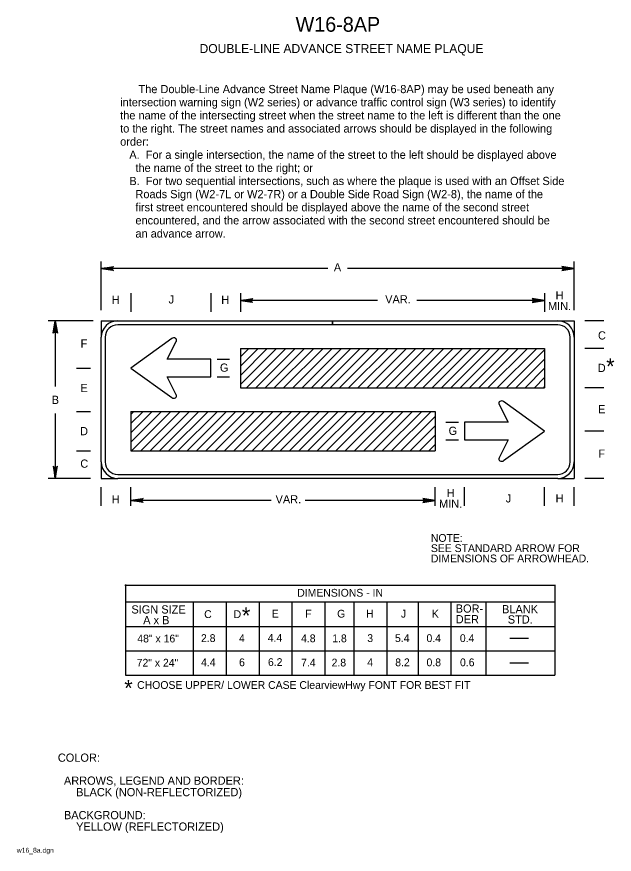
# Model space of a CAD drawing. Extents: x 0.013 to 0.195, y 0.004 to 0.259.
import ezdxf

# ---------------------------------------------------------------- set-up
doc = ezdxf.new("R2010")
doc.units = 0
for name, color, linetype in [('1', 7, 'Continuous'), ('2', 7, 'Continuous'), ('3', 7, 'Continuous')]:
    doc.layers.add(name, color=color, linetype=linetype)

# ---------------------------------------------------------------- blocks, each defined once
blk = doc.blocks.new('RARROW')
at = {"layer": '3'}
for p, q in [((-2.156, 0.285), (-2.2665, 0.384625)), ((-2.2665, 0.384625), (0, 0)), ((0, 0), (-2.2665, -0.379125)), ((-2.156, 0.285), (-2.075625, 0.12075)), ((0, 0), (-2.156, 0.285)), ((-2.14975, -0.2705), (0, 0)), ((-2.075625, 0.12075), (0, 0)), ((0, 0), (-2.074, -0.108)), ((-2.2665, -0.379125), (-2.14975, -0.2705)), ((-2.074, -0.108), (-2.14975, -0.2705))]:
    blk.add_line(p, q, dxfattribs=at)

msp = doc.modelspace()

# ---------------------------------------------------------------- linework, layer by layer
at = {"layer": '1'}
for p, q in [((0.04735, 0.17484), (0.04735, 0.16912)), ((0.0717, 0.17484), (0.0717, 0.16912)), ((0.0807, 0.17484), (0.0807, 0.16912)), ((0.17335, 0.17484), (0.17335, 0.16912)), ((0.02436, 0.16643), (0.02436, 0.14645)), ((0.03835, 0.16643), (0.03835, 0.16143)), ((0.04335, 0.16643), (0.10877, 0.16643)), ((0.10877, 0.16643), (0.10877, 0.16523)), ((0.10877, 0.16523), (0.10877, 0.16643)), ((0.10877, 0.16643), (0.17735, 0.16643)), ((0.18235, 0.16643), (0.18235, 0.16143)), ((0.10877, 0.16523), (0.04335, 0.16523)), ((0.17735, 0.16523), (0.10877, 0.16523)), ((0.03835, 0.12343), (0.03835, 0.16143)), ((0.03955, 0.16143), (0.03955, 0.12343)), ((0.05982, 0.16103), (0.04735, 0.15203)), ((0.18115, 0.12343), (0.18115, 0.16143)), ((0.18235, 0.16143), (0.18235, 0.12343)), ((0.05841, 0.15473), (0.06118, 0.16015)), ((0.0807, 0.15803), (0.0807, 0.14603)), ((0.0807, 0.15547), (0.08325, 0.15803)), ((0.0807, 0.15265), (0.08608, 0.15803)), ((0.0807, 0.14982), (0.08891, 0.15803)), ((0.0807, 0.14699), (0.09174, 0.15803)), ((0.08257, 0.14603), (0.09457, 0.15803)), ((0.08539, 0.14603), (0.09739, 0.15803)), ((0.08822, 0.14603), (0.10022, 0.15803)), ((0.09105, 0.14603), (0.10305, 0.15803)), ((0.09388, 0.14603), (0.10588, 0.15803)), ((0.09671, 0.14603), (0.10871, 0.15803)), ((0.09954, 0.14603), (0.11154, 0.15803)), ((0.10237, 0.14603), (0.11437, 0.15803)), ((0.10519, 0.14603), (0.11719, 0.15803)), ((0.10802, 0.14603), (0.12002, 0.15803)), ((0.11085, 0.14603), (0.12285, 0.15803)), ((0.11368, 0.14603), (0.12568, 0.15803)), ((0.11651, 0.14603), (0.12851, 0.15803)), ((0.11934, 0.14603), (0.13134, 0.15803)), ((0.12216, 0.14603), (0.13416, 0.15803)), ((0.12499, 0.14603), (0.13699, 0.15803)), ((0.12782, 0.14603), (0.13982, 0.15803)), ((0.13065, 0.14603), (0.14265, 0.15803)), ((0.13348, 0.14603), (0.14548, 0.15803)), ((0.13631, 0.14603), (0.14831, 0.15803)), ((0.13913, 0.14603), (0.15113, 0.15803)), ((0.14196, 0.14603), (0.15396, 0.15803)), ((0.14479, 0.14603), (0.15679, 0.15803)), ((0.14762, 0.14603), (0.15962, 0.15803)), ((0.15045, 0.14603), (0.16245, 0.15803)), ((0.15328, 0.14603), (0.16528, 0.15803)), ((0.15611, 0.14603), (0.16811, 0.15803)), ((0.15893, 0.14603), (0.17093, 0.15803)), ((0.16176, 0.14603), (0.17335, 0.15761)), ((0.17335, 0.15803), (0.17335, 0.14603)), ((0.0717, 0.15473), (0.05841, 0.15473)), ((0.0717, 0.14933), (0.0717, 0.15473)), ((0.16459, 0.14603), (0.17335, 0.15479)), ((0.04735, 0.15203), (0.05982, 0.14303)), ((0.16742, 0.14603), (0.17335, 0.15196)), ((0.06118, 0.1439), (0.05841, 0.14933)), ((0.05841, 0.14933), (0.0717, 0.14933)), ((0.17025, 0.14603), (0.17335, 0.14913)), ((0.17308, 0.14603), (0.17335, 0.1463)), ((0.15952, 0.14095), (0.16229, 0.13553)), ((0.17335, 0.13283), (0.16087, 0.14183)), ((0.02436, 0.13816), (0.02436, 0.11843)), ((0.04735, 0.13883), (0.04735, 0.12683)), ((0.04735, 0.13793), (0.04825, 0.13883)), ((0.04735, 0.1351), (0.05108, 0.13883)), ((0.04735, 0.13227), (0.0539, 0.13883)), ((0.04735, 0.12944), (0.05673, 0.13883)), ((0.04756, 0.12683), (0.05956, 0.13883)), ((0.05039, 0.12683), (0.06239, 0.13883)), ((0.05322, 0.12683), (0.06522, 0.13883)), ((0.05605, 0.12683), (0.06805, 0.13883)), ((0.05887, 0.12683), (0.07087, 0.13883)), ((0.0617, 0.12683), (0.0737, 0.13883)), ((0.06453, 0.12683), (0.07653, 0.13883)), ((0.06736, 0.12683), (0.07936, 0.13883)), ((0.07019, 0.12683), (0.08219, 0.13883)), ((0.07302, 0.12683), (0.08502, 0.13883)), ((0.07585, 0.12683), (0.08785, 0.13883)), ((0.07867, 0.12683), (0.09067, 0.13883)), ((0.0815, 0.12683), (0.0935, 0.13883)), ((0.08433, 0.12683), (0.09633, 0.13883)), ((0.08716, 0.12683), (0.09916, 0.13883)), ((0.08999, 0.12683), (0.10199, 0.13883)), ((0.09282, 0.12683), (0.10482, 0.13883)), ((0.09564, 0.12683), (0.10764, 0.13883)), ((0.09847, 0.12683), (0.11047, 0.13883)), ((0.1013, 0.12683), (0.1133, 0.13883)), ((0.10413, 0.12683), (0.11613, 0.13883)), ((0.10696, 0.12683), (0.11896, 0.13883)), ((0.10979, 0.12683), (0.12179, 0.13883)), ((0.11261, 0.12683), (0.12461, 0.13883)), ((0.11544, 0.12683), (0.12744, 0.13883)), ((0.11827, 0.12683), (0.13027, 0.13883)), ((0.1211, 0.12683), (0.1331, 0.13883)), ((0.12393, 0.12683), (0.13593, 0.13883)), ((0.12676, 0.12683), (0.13876, 0.13883)), ((0.14, 0.13883), (0.14, 0.12683)), ((0.12959, 0.12683), (0.14, 0.13724)), ((0.149, 0.13553), (0.149, 0.13013)), ((0.16229, 0.13553), (0.149, 0.13553)), ((0.13241, 0.12683), (0.14, 0.13441)), ((0.16087, 0.12383), (0.17335, 0.13283)), ((0.13524, 0.12683), (0.14, 0.13158)), ((0.149, 0.13013), (0.16229, 0.13013)), ((0.16229, 0.13013), (0.15952, 0.1247)), ((0.13807, 0.12683), (0.14, 0.12876)), ((0.03835, 0.12343), (0.03835, 0.11843)), ((0.18235, 0.12343), (0.18235, 0.11843)), ((0.04335, 0.11963), (0.17735, 0.11963)), ((0.17735, 0.11843), (0.04335, 0.11843)), ((0.03835, 0.11002), (0.03835, 0.11574)), ((0.04735, 0.11002), (0.04735, 0.11574)), ((0.14, 0.11002), (0.14, 0.11574)), ((0.149, 0.11002), (0.149, 0.11574)), ((0.17335, 0.11002), (0.17335, 0.11574)), ((0.18235, 0.11002), (0.18235, 0.11574))]:
    msp.add_line(p, q, dxfattribs=at)
for centre, radius, start, end in [((0.04335, 0.16143), 0.005, 90, 180), ((0.17735, 0.16143), 0.005, 0, 90), ((0.04335, 0.16143), 0.0038, 90, 180), ((0.17735, 0.16143), 0.0038, 0, 90), ((0.04335, 0.12343), 0.005, 180, 270), ((0.04335, 0.12343), 0.0038, 180, 270), ((0.17735, 0.12343), 0.0038, 270, 0), ((0.17735, 0.12343), 0.005, 270, 0)]:
    msp.add_arc(centre, radius, start, end, dxfattribs=at)
for centre, major_axis, start_param, end_param in [((0.06041, 0.16048), (-0.000902, 0), 2.724701, 5.443422), ((0.06041, 0.14358), (-0.000902, 0), 0.839763, 3.558484), ((0.16029, 0.14128), (0.000902, 0), 0.839763, 3.558484), ((0.16029, 0.12438), (0.000902, 0), 2.724701, 5.443422)]:
    msp.add_ellipse(centre, major_axis=major_axis, ratio=0.831622, start_param=start_param, end_param=end_param, dxfattribs=at)
at = {"layer": '3'}
for p, q in [((0.03835, 0.16969), (0.03835, 0.1845)), ((0.18235, 0.16969), (0.18235, 0.1845)), ((0.10736, 0.18236), (0.03835, 0.18236)), ((0.18235, 0.18236), (0.11335, 0.18236)), ((0.12242, 0.17263), (0.0807, 0.17263)), ((0.17335, 0.17263), (0.13443, 0.17263)), ((0.03585, 0.16643), (0.02222, 0.16643)), ((0.03835, 0.16643), (0.04335, 0.16643)), ((0.17735, 0.16643), (0.18235, 0.16643)), ((0.19135, 0.16643), (0.18563, 0.16643)), ((0.0807, 0.15803), (0.17335, 0.15803)), ((0.19135, 0.15803), (0.18563, 0.15803)), ((0.07367, 0.15473), (0.07742, 0.15473)), ((0.03077, 0.15203), (0.03506, 0.15203)), ((0.07367, 0.14933), (0.07742, 0.14933)), ((0.0807, 0.14603), (0.17335, 0.14603)), ((0.19135, 0.14603), (0.18563, 0.14603)), ((0.03077, 0.13883), (0.03506, 0.13883)), ((0.04735, 0.13883), (0.14, 0.13883)), ((0.14328, 0.13553), (0.14712, 0.13553)), ((0.19135, 0.13283), (0.18563, 0.13283)), ((0.14328, 0.13013), (0.14712, 0.13013)), ((0.03077, 0.12683), (0.03506, 0.12683)), ((0.04735, 0.12683), (0.14, 0.12683)), ((0.03506, 0.11843), (0.02222, 0.11843)), ((0.03835, 0.11843), (0.04335, 0.11843)), ((0.17735, 0.11843), (0.18235, 0.11843)), ((0.19135, 0.11843), (0.18563, 0.11843)), ((0.09011, 0.11172), (0.04735, 0.11172)), ((0.14, 0.11172), (0.1004, 0.11172)), ((0.04549, 0.08589), (0.17645, 0.08589)), ((0.04573, 0.08615), (0.04573, 0.05851)), ((0.17645, 0.08596), (0.17645, 0.05851)), ((0.17645, 0.08076), (0.04573, 0.08076)), ((0.06635, 0.08076), (0.06635, 0.05851)), ((0.0864, 0.08076), (0.0864, 0.05851)), ((0.10646, 0.08076), (0.10646, 0.05851)), ((0.11525, 0.08076), (0.11525, 0.05851)), ((0.15543, 0.08076), (0.15543, 0.05851)), ((0.04573, 0.07326), (0.17645, 0.07326)), ((0.16848, 0.06968), (0.16276, 0.06968)), ((0.04574, 0.06589), (0.17645, 0.06589)), ((0.16848, 0.0621), (0.16276, 0.0621)), ((0.04573, 0.05851), (0.17645, 0.05851))]:
    msp.add_line(p, q, dxfattribs=at)
for points in [[(0.07638, 0.08076), (0.07638, 0.05851)], [(0.09643, 0.08076), (0.09643, 0.05851)], [(0.12535, 0.08076), (0.12535, 0.05851)], [(0.1348, 0.08076), (0.1348, 0.05851)], [(0.14484, 0.08076), (0.14484, 0.05851)]]:
    msp.add_lwpolyline(points, dxfattribs=at)

# ---------------------------------------------------------------- block references
at = {"layer": '3', "xscale": 0.0016545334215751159}
for p, yscale, rotation in [((0.03835, 0.18236), 0.0016366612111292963, 180), ((0.0807, 0.17263), 0.0016366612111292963, 180), ((0.02436, 0.16643), 0.0016366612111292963, 89.99999999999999), ((0.02436, 0.11843), -0.0016366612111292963, -89.99999999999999), ((0.04735, 0.11172), 0.0016366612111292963, 180)]:
    msp.add_blockref('RARROW', p, dxfattribs=dict(at, yscale=yscale, rotation=rotation))
at = {"layer": '3', "xscale": 0.0016545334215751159, "yscale": -0.0016366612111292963}
for p in [(0.18235, 0.18236), (0.17335, 0.17263), (0.14, 0.11172)]:
    msp.add_blockref('RARROW', p, dxfattribs=at)

# ---------------------------------------------------------------- texts
at = {"layer": '1'}
for s, height, p in [('W16-8AP', 0.0045, (0.09752, 0.2545)), ('DOUBLE-LINE ADVANCE STREET NAME PLAQUE', 0.0027503, (0.06828, 0.248)), ('CHOOSE UPPER/ LOWER CASE ClearviewHwy FONT FOR BEST FIT', 0.0023752, (0.04928, 0.0543)), ('COLOR:', 0.0025, (0.02513, 0.0321)), ('  ARROWS, LEGEND AND BORDER:', 0.0024998, (0.02513, 0.0251)), ('      BLACK (NON-REFLECTORIZED)', 0.0024998, (0.02513, 0.0216)), ('  BACKGROUND:', 0.0024998, (0.02513, 0.0146)), ('      YELLOW (REFLECTORIZED)', 0.0024998, (0.02513, 0.0111)), ('w16_8a.dgn', 0.0015, (0.01263, 0.00438))]:
    msp.add_text(s, height=height, dxfattribs=at).set_placement(p)
at = {"layer": '2'}
for s, height, p in [('      The Double-Line Advance Street Name Plaque (W16-8AP) may be used beneath any', 0.0024998, (0.04411, 0.23579)), ('intersection warning sign (W2 series) or advance traffic control sign (W3 series) to identify', 0.0024998, (0.04411, 0.23179)), ('the name of the intersecting street when the street name to the left is different than the one', 0.0024998, (0.04411, 0.22779)), ('to the right. The street names and associated arrows should be displayed in the following', 0.0024998, (0.04411, 0.22379)), ('order:', 0.0025, (0.04411, 0.21979)), ('   A.  For a single intersection, the name of the street to the left should be displayed above', 0.0024998, (0.04411, 0.21579)), ('     the name of the street to the right; or', 0.0024998, (0.04411, 0.21179)), ('   B.  For two sequential intersections, such as where the plaque is used with an Offset Side ', 0.0024998, (0.04411, 0.20779)), ('     Roads Sign (W2-7L or W2-7R) or a Double Side Road Sign (W2-8), the name of the ', 0.0024998, (0.04411, 0.20379)), ('     first street encountered should be displayed above the name of the second street ', 0.0024998, (0.04411, 0.1998)), ('     encountered, and the arrow associated with the second street encountered should be ', 0.0024998, (0.04411, 0.1958)), ('     an advance arrow. ', 0.0024998, (0.04411, 0.1918))]:
    msp.add_text(s, height=height, dxfattribs=at).set_placement(p)
at = {"layer": '3'}
for s, height, p in [('A', 0.0025, (0.10917, 0.18147)), ('H', 0.0025, (0.04154, 0.1716)), ('J', 0.0025, (0.05886, 0.17171)), ('H', 0.0025, (0.07489, 0.1716)), ('VAR.', 0.0025, (0.1248, 0.17174)), ('H', 0.0025, (0.17669, 0.17294)), ('MIN.', 0.0025, (0.17437, 0.16969)), ('F', 0.0025, (0.03206, 0.15827)), ('C', 0.0025, (0.1896, 0.16074)), ('D', 0.0025, (0.18953, 0.15083)), ('*', 0.00493, (0.19209, 0.15011)), ('E', 0.0025, (0.03203, 0.14472)), ('B', 0.0025, (0.02328, 0.14111)), ('E', 0.0025, (0.18966, 0.13825)), ('D', 0.0025, (0.0319, 0.13157)), ('G', 0.0025, (0.14411, 0.13167)), ('F', 0.0025, (0.1897, 0.12471)), ('C', 0.0025, (0.03197, 0.12167)), ('H', 0.0025, (0.14352, 0.11271)), ('H', 0.0025, (0.04154, 0.1108)), ('VAR.', 0.0025, (0.09143, 0.1108)), ('J', 0.0025, (0.16152, 0.11109)), ('H', 0.0025, (0.17669, 0.11109)), ('MIN.', 0.0025, (0.1412, 0.10946)), ('NOTE:', 0.002375, (0.13872, 0.0991)), ('SEE STANDARD ARROW FOR', 0.0023752, (0.13872, 0.09598)), ('DIMENSIONS OF ARROWHEAD.', 0.0023752, (0.13872, 0.09285)), ('DIMENSIONS - IN', 0.0023752, (0.09802, 0.08239)), ('SIGN SIZE', 0.0025, (0.04753, 0.07726)), ('*', 0.00493, (0.08117, 0.07418)), ('BOR-', 0.0025, (0.14629, 0.07753)), ('BLANK', 0.0025, (0.16038, 0.07733)), ('C', 0.00238, (0.06969, 0.07588)), ('D', 0.00238, (0.07864, 0.07587)), ('F', 0.00238, (0.10046, 0.07601)), ('G', 0.00238, (0.11017, 0.07601)), ('H', 0.00238, (0.11897, 0.07601)), ('J', 0.00238, (0.12959, 0.07601)), ('K', 0.00238, (0.13899, 0.07601)), ('DER', 0.0025, (0.14629, 0.07428)), ('STD.', 0.0025, (0.16213, 0.0742)), ('A x B', 0.0025, (0.05112, 0.07401)), ('48" x 16"', 0.002375, (0.04933, 0.06845)), ('2.8', 0.002375, (0.06872, 0.06858)), ('4', 0.00238, (0.08029, 0.06858)), ('4.4', 0.002375, (0.08904, 0.06865)), ('4.8', 0.002375, (0.09919, 0.06851)), ('1.8', 0.002375, (0.10869, 0.06851)), ('5.4', 0.002375, (0.12779, 0.06858)), ('0.4', 0.002375, (0.13738, 0.06857)), ('0.4', 0.002375, (0.14754, 0.06857)), ('72" x 24"', 0.002375, (0.04913, 0.06108)), ('4.4', 0.002375, (0.06874, 0.0612)), ('6', 0.00238, (0.08031, 0.0612)), ('6.2', 0.002375, (0.08911, 0.06127)), ('7.4', 0.002375, (0.0992, 0.06113)), ('2.8', 0.002375, (0.10849, 0.06113)), ('8.2', 0.002375, (0.12786, 0.0612)), ('0.8', 0.002375, (0.13739, 0.0612)), ('0.6', 0.002375, (0.14759, 0.0612)), ('*', 0.00493, (0.04535, 0.0521))]:
    msp.add_text(s, height=height, dxfattribs=at).set_placement(p)
for s, height, p in [('G', 0.0025, (0.07448, 0.15092)), ('E', 0.00238, (0.09024, 0.07601)), ('3', 0.00238, (0.11934, 0.06858)), ('4', 0.00238, (0.11933, 0.0612))]:
    msp.add_text(s, height=height, rotation=360, dxfattribs=at).set_placement(p)

doc.saveas('drawing.dxf')
